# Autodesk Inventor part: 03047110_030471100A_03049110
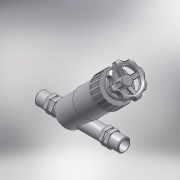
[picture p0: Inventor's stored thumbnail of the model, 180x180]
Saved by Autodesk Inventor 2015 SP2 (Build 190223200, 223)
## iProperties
Created: 2017-05
Part Number: 03047110_030471100A_03049110
Material: Generic
Description: PLASSON ANGLE SEAT VALVE 1"-1"
Document SubType Name: Modeling
Designer: KIM
Mass: 184.302 g
Surface Area: 375.869 cm^2
Volume: 184.302 cm^3
Density: 1 g/cm^3
Appearance: Default
Author: KIM
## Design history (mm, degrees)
derived "03047.ipt"
feature "Solid1::03047.ipt"
tag "TaggingFeature1"
body "Solid1"
other parameters: "d1" = 33.249, "d2" = 36, "d3" = 26.5992, "d6" = 17, "d8" = 1.7, "d12" = 0, "d14" = -8.5, "d15" = 3.4, "d16" = 0, "d17" = 41.58, "d19" = 132.3, "d20" = 52.29, "d21" = 135 deg, "d22" = 54.81, "d23" = 25.2, "d24" = 59.85, "d25" = 15.12, "d26" = 90 deg, "d27" = 44.1, "d28" = 70 deg, "d29" = 18.9, "d30" = 15.12, "d31" = 18.9, "d32" = 63, "d33" = 44.1, "d34" = 135 deg, "d35" = 2, "d36" = 126, "d39" = 59.5, "d40" = 1.4, "d42" = 1, "d43" = 4.2, "d44" = 4.2, "d46" = 0, "d48" = 360 deg, "d50" = 0.7, "d51" = 0.7, "d53" = 360 deg, "d69" = 53.55, "d70" = 4.2, "d71" = 4.2, "d72" = 8.4, "d74" = 0, "d75" = 0.7, "d77" = 360 deg, "d80" = 58.0545, "d81" = 5.6, "d82" = 2.8, "d83" = 22.68, "d84" = 0, "d86" = 360 deg, "d88" = 1.4, "d89" = 5.04, "d90" = 0.7, "R_" = 33.249, "E_" = 36, "d13" = 17, "d67" = 63, "d68" = 44.1, "d79" = 59.85
